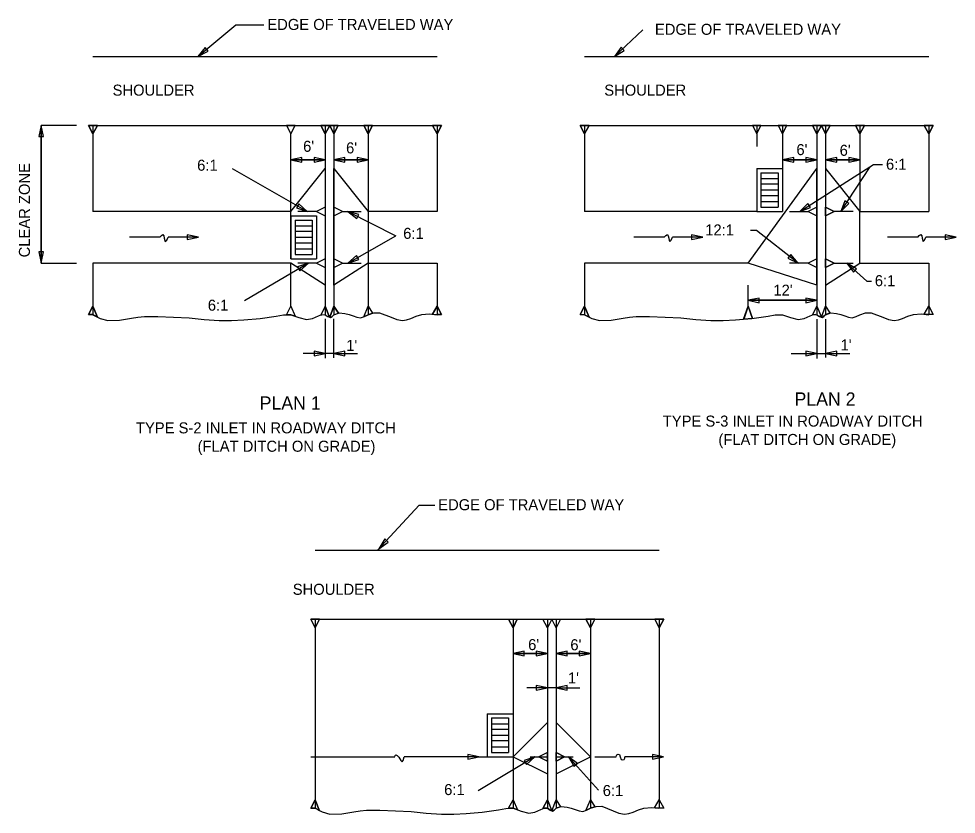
# Model space of a CAD drawing. Extents: x -437.4 to -407.9, y -458.1 to -438.
# Drawn here: x -437.39 to -424.64, y -448.87 to -438.05 of the extents above; entities that cross this region are included whole.
import ezdxf

# ---------------------------------------------------------------- set-up
doc = ezdxf.new("R2010")
doc.units = 0
for name, color, linetype in [('Common-Notes', 7, 'Continuous'), ('Level 4', 7, 'Continuous'), ('Level 45', 7, 'Continuous')]:
    doc.layers.add(name, color=color, linetype=linetype)

msp = doc.modelspace()

# ---------------------------------------------------------------- linework, layer by layer
at = {"layer": 'Level 4'}
for p, q in [((-434.95, -438.564), (-434.433, -438.133)), ((-434.433, -438.133), (-434.053, -438.133)), ((-429.285, -438.564), (-428.902, -438.202)), ((-436.378, -438.564), (-431.699, -438.564)), ((-429.692, -438.564), (-425.013, -438.564)), ((-436.604, -439.499), (-437.081, -439.499)), ((-437.08, -441.372), (-437.08, -439.5)), ((-437.08, -439.5), (-437.08, -441.372)), ((-436.378, -439.616), (-436.439, -439.499)), ((-436.439, -439.499), (-436.378, -439.499)), ((-436.378, -439.499), (-431.699, -439.499)), ((-436.318, -439.499), (-436.378, -439.616)), ((-436.378, -439.499), (-436.378, -440.67)), ((-433.746, -439.499), (-433.687, -439.616)), ((-433.687, -439.616), (-433.63, -439.499)), ((-433.22, -439.616), (-433.28, -439.499)), ((-433.159, -439.499), (-433.22, -439.616)), ((-433.22, -439.499), (-433.22, -442.073)), ((-433.103, -439.616), (-433.159, -439.499)), ((-433.042, -439.499), (-433.103, -439.616)), ((-433.103, -439.499), (-433.103, -442.073)), ((-432.635, -439.616), (-432.696, -439.499)), ((-432.575, -439.499), (-432.635, -439.616)), ((-432.635, -439.499), (-432.635, -442.073)), ((-431.699, -439.616), (-431.76, -439.499)), ((-431.699, -439.499), (-431.639, -439.499)), ((-431.639, -439.499), (-431.699, -439.616)), ((-431.699, -439.499), (-431.699, -440.67)), ((-429.692, -439.616), (-429.753, -439.499)), ((-429.753, -439.499), (-429.692, -439.499)), ((-429.692, -439.499), (-425.013, -439.499)), ((-429.632, -439.499), (-429.692, -439.616)), ((-429.692, -439.499), (-429.692, -440.67)), ((-427.411, -439.499), (-427.352, -439.616)), ((-427.352, -439.616), (-427.294, -439.499)), ((-427.352, -439.499), (-427.352, -439.785)), ((-427.06, -439.499), (-427.001, -439.616)), ((-427.001, -439.616), (-426.944, -439.499)), ((-427.001, -439.499), (-427.001, -440.67)), ((-426.534, -439.616), (-426.594, -439.499)), ((-426.473, -439.499), (-426.534, -439.616)), ((-426.534, -439.499), (-426.534, -442.073)), ((-426.417, -439.616), (-426.473, -439.499)), ((-426.355, -439.499), (-426.417, -439.616)), ((-426.417, -439.499), (-426.417, -442.073)), ((-425.948, -439.616), (-426.01, -439.499)), ((-425.888, -439.499), (-425.948, -439.616)), ((-425.948, -439.499), (-425.948, -440.67)), ((-425.013, -439.616), (-425.074, -439.499)), ((-425.013, -439.499), (-424.953, -439.499)), ((-424.953, -439.499), (-425.013, -439.616)), ((-425.013, -439.499), (-425.013, -440.67)), ((-433.687, -440.67), (-433.687, -439.616)), ((-433.688, -439.968), (-433.22, -439.968)), ((-433.22, -439.968), (-433.688, -439.968)), ((-433.103, -439.968), (-432.635, -439.968)), ((-432.635, -439.968), (-433.103, -439.968)), ((-427.001, -439.968), (-426.534, -439.968)), ((-426.534, -439.968), (-427.001, -439.968)), ((-426.767, -440.67), (-425.766, -440.033)), ((-426.417, -439.968), (-425.949, -439.968)), ((-425.949, -439.968), (-426.417, -439.968)), ((-426.209, -440.67), (-425.811, -440.061)), ((-425.766, -440.033), (-425.64, -440.033)), ((-433.463, -440.67), (-434.48, -440.09)), ((-433.687, -440.67), (-433.22, -440.085)), ((-433.22, -440.085), (-433.22, -441.671)), ((-433.103, -441.671), (-433.103, -440.085)), ((-433.103, -440.085), (-432.635, -440.67)), ((-427.469, -441.372), (-426.534, -440.085)), ((-427.352, -440.085), (-427.001, -440.085)), ((-427.352, -440.085), (-427.352, -440.67)), ((-427.294, -440.143), (-427.06, -440.143)), ((-427.294, -440.143), (-427.294, -440.612)), ((-427.06, -440.143), (-427.06, -440.612)), ((-427.001, -440.085), (-427.001, -440.67)), ((-426.534, -441.671), (-426.534, -440.085)), ((-426.417, -440.085), (-425.948, -440.67)), ((-426.417, -440.085), (-426.417, -441.671)), ((-427.294, -440.221), (-427.06, -440.221)), ((-427.06, -440.3), (-427.294, -440.3)), ((-427.294, -440.377), (-427.06, -440.377)), ((-427.06, -440.455), (-427.294, -440.455)), ((-427.294, -440.533), (-427.06, -440.533)), ((-433.687, -440.67), (-436.378, -440.67)), ((-433.687, -441.313), (-433.687, -440.67)), ((-433.337, -440.67), (-433.594, -440.67)), ((-433.22, -440.612), (-433.337, -440.67)), ((-433.337, -440.67), (-433.22, -440.729)), ((-432.986, -440.67), (-433.103, -440.612)), ((-433.103, -440.729), (-432.986, -440.67)), ((-432.986, -440.67), (-432.729, -440.67)), ((-432.912, -440.67), (-432.26, -441.003)), ((-432.635, -440.67), (-432.635, -441.372)), ((-431.699, -440.67), (-432.635, -440.67)), ((-427.352, -440.67), (-429.692, -440.67)), ((-427.352, -440.67), (-427.001, -440.67)), ((-427.294, -440.612), (-427.06, -440.612)), ((-426.908, -440.67), (-426.651, -440.67)), ((-426.534, -440.612), (-426.651, -440.67)), ((-426.651, -440.67), (-426.534, -440.729)), ((-426.3, -440.67), (-426.417, -440.612)), ((-426.417, -440.729), (-426.3, -440.67)), ((-426.042, -440.67), (-426.3, -440.67)), ((-425.948, -441.372), (-425.948, -440.67)), ((-425.948, -440.67), (-425.013, -440.67)), ((-433.687, -440.729), (-433.687, -441.313)), ((-433.687, -440.729), (-433.337, -440.729)), ((-433.63, -440.786), (-433.396, -440.786)), ((-433.63, -440.786), (-433.63, -441.255)), ((-433.396, -440.786), (-433.396, -441.255)), ((-433.337, -440.729), (-433.337, -441.313)), ((-433.63, -440.865), (-433.396, -440.865)), ((-433.396, -440.943), (-433.63, -440.943)), ((-427.357, -440.927), (-427.435, -440.927)), ((-426.788, -441.372), (-427.357, -440.927)), ((-435.469, -441.02), (-435.88, -441.02)), ((-434.945, -441.021), (-435.357, -441.021)), ((-433.63, -441.02), (-433.396, -441.02)), ((-433.396, -441.099), (-433.63, -441.099)), ((-432.911, -441.372), (-432.26, -441.003)), ((-428.609, -441.02), (-429.021, -441.02)), ((-428.085, -441.021), (-428.497, -441.021)), ((-425.163, -441.02), (-425.574, -441.02)), ((-424.638, -441.021), (-425.05, -441.021)), ((-433.63, -441.177), (-433.396, -441.177)), ((-433.687, -441.313), (-433.337, -441.313)), ((-433.63, -441.255), (-433.396, -441.255)), ((-433.22, -441.313), (-433.337, -441.372)), ((-432.986, -441.372), (-433.103, -441.313)), ((-426.534, -441.313), (-426.651, -441.372)), ((-426.3, -441.372), (-426.417, -441.313)), ((-437.081, -441.372), (-436.604, -441.372)), ((-436.378, -441.372), (-436.378, -442.073)), ((-433.687, -441.372), (-436.378, -441.372)), ((-433.449, -441.372), (-434.315, -441.883)), ((-433.22, -441.671), (-433.687, -441.372)), ((-433.687, -441.957), (-433.687, -441.372)), ((-433.337, -441.372), (-433.594, -441.372)), ((-433.337, -441.372), (-433.22, -441.43)), ((-432.635, -441.372), (-433.103, -441.671)), ((-433.103, -441.43), (-432.986, -441.372)), ((-432.986, -441.372), (-432.729, -441.372)), ((-432.635, -441.372), (-431.699, -441.372)), ((-431.699, -441.372), (-431.699, -442.073)), ((-429.692, -441.372), (-429.692, -442.073)), ((-427.469, -441.372), (-429.692, -441.372)), ((-426.534, -441.671), (-427.469, -441.372)), ((-426.651, -441.372), (-426.908, -441.372)), ((-426.651, -441.372), (-426.534, -441.43)), ((-426.417, -441.671), (-425.948, -441.372)), ((-426.417, -441.43), (-426.3, -441.372)), ((-426.3, -441.372), (-426.042, -441.372)), ((-426.128, -441.372), (-425.854, -441.618)), ((-425.948, -441.372), (-425.013, -441.372)), ((-425.013, -441.372), (-425.013, -442.073)), ((-427.469, -441.957), (-427.469, -441.671)), ((-425.854, -441.618), (-425.792, -441.618)), ((-436.378, -441.957), (-436.439, -442.073)), ((-436.318, -442.106), (-436.378, -441.957)), ((-433.748, -442.074), (-433.687, -441.957)), ((-433.687, -441.957), (-433.628, -442.094)), ((-433.22, -441.957), (-433.281, -442.078)), ((-433.22, -441.957), (-433.161, -442.106)), ((-433.158, -442.107), (-433.103, -441.957)), ((-433.103, -441.957), (-433.041, -442.052)), ((-432.695, -442.103), (-432.635, -441.957)), ((-432.635, -441.957), (-432.575, -442.051)), ((-431.76, -442.064), (-431.699, -441.957)), ((-431.699, -441.957), (-431.639, -442.073)), ((-429.692, -441.957), (-429.753, -442.073)), ((-429.632, -442.106), (-429.692, -441.957)), ((-427.469, -441.957), (-427.528, -442.135)), ((-427.469, -441.878), (-426.534, -441.878)), ((-426.534, -441.878), (-427.469, -441.878)), ((-427.411, -442.126), (-427.469, -441.957)), ((-426.534, -441.957), (-426.594, -442.076)), ((-426.534, -441.957), (-426.473, -442.109)), ((-426.473, -442.109), (-426.417, -441.957)), ((-426.417, -441.957), (-426.356, -442.05)), ((-425.075, -442.066), (-425.013, -441.957)), ((-425.013, -441.957), (-424.953, -442.073)), ((-436.439, -442.073), (-436.378, -442.073)), ((-431.639, -442.073), (-431.699, -442.073)), ((-429.753, -442.073), (-429.692, -442.073)), ((-424.953, -442.073), (-425.013, -442.073)), ((-433.22, -442.128), (-433.22, -442.666)), ((-433.103, -442.658), (-433.103, -442.128)), ((-426.534, -442.134), (-426.534, -442.669)), ((-426.417, -442.134), (-426.417, -442.656)), ((-433.103, -442.602), (-433.521, -442.602)), ((-433.103, -442.602), (-432.781, -442.602)), ((-426.882, -442.602), (-426.086, -442.602)), ((-432.509, -445.276), (-431.944, -444.663)), ((-431.944, -444.663), (-431.73, -444.663)), ((-433.357, -445.275), (-428.678, -445.275)), ((-433.357, -446.329), (-433.417, -446.212)), ((-433.417, -446.212), (-433.357, -446.212)), ((-433.296, -446.212), (-433.357, -446.329)), ((-433.357, -446.212), (-433.357, -448.784)), ((-433.357, -446.212), (-428.678, -446.212)), ((-430.725, -446.212), (-430.666, -446.329)), ((-430.666, -446.329), (-430.608, -446.212)), ((-430.666, -446.212), (-430.666, -448.785)), ((-430.198, -446.329), (-430.259, -446.212)), ((-430.138, -446.212), (-430.198, -446.329)), ((-430.198, -446.212), (-430.198, -448.784)), ((-430.081, -446.329), (-430.138, -446.212)), ((-430.021, -446.212), (-430.081, -446.329)), ((-430.081, -446.212), (-430.081, -448.784)), ((-429.613, -446.329), (-429.674, -446.212)), ((-429.552, -446.212), (-429.614, -446.329)), ((-429.614, -446.212), (-429.614, -448.784)), ((-428.678, -446.329), (-428.738, -446.212)), ((-428.678, -446.212), (-428.617, -446.212)), ((-428.617, -446.212), (-428.678, -446.329)), ((-428.678, -446.212), (-428.678, -448.784)), ((-430.666, -446.679), (-430.198, -446.679)), ((-430.198, -446.679), (-430.666, -446.679)), ((-430.081, -446.679), (-429.613, -446.679)), ((-429.613, -446.679), (-430.081, -446.679)), ((-430.081, -447.147), (-430.476, -447.147)), ((-430.081, -447.147), (-429.758, -447.147)), ((-431.016, -447.499), (-431.016, -448.083)), ((-431.016, -447.499), (-430.666, -447.499)), ((-430.959, -447.557), (-430.725, -447.557)), ((-430.959, -447.557), (-430.959, -448.024)), ((-430.725, -447.557), (-430.725, -448.024)), ((-430.666, -447.499), (-430.666, -448.083)), ((-430.959, -447.635), (-430.725, -447.635)), ((-430.725, -447.713), (-430.959, -447.713)), ((-430.198, -447.616), (-430.666, -448.083)), ((-430.198, -447.616), (-430.198, -448.317)), ((-429.614, -448.083), (-430.081, -447.616)), ((-430.081, -447.616), (-430.081, -448.317)), ((-430.959, -447.79), (-430.725, -447.79)), ((-430.725, -447.869), (-430.959, -447.869)), ((-430.959, -447.947), (-430.725, -447.947)), ((-433.416, -448.083), (-432.275, -448.083)), ((-431.129, -448.083), (-432.148, -448.083)), ((-430.367, -448.083), (-431.141, -448.549)), ((-431.129, -448.083), (-431.016, -448.083)), ((-431.016, -448.083), (-430.666, -448.083)), ((-430.959, -448.024), (-430.725, -448.024)), ((-430.666, -448.083), (-430.198, -448.317)), ((-430.432, -448.083), (-430.198, -448.083)), ((-430.198, -448.024), (-430.315, -448.083)), ((-430.315, -448.083), (-430.198, -448.142)), ((-429.965, -448.083), (-430.081, -448.024)), ((-430.081, -448.317), (-429.613, -448.083)), ((-430.081, -448.083), (-429.848, -448.083)), ((-430.081, -448.142), (-429.965, -448.083)), ((-429.912, -448.083), (-429.503, -448.538)), ((-429.555, -448.083), (-429.262, -448.083)), ((-428.619, -448.083), (-429.145, -448.083)), ((-433.357, -448.668), (-433.417, -448.784)), ((-433.296, -448.819), (-433.357, -448.668)), ((-430.727, -448.785), (-430.666, -448.668)), ((-430.666, -448.668), (-430.607, -448.806)), ((-430.198, -448.668), (-430.259, -448.789)), ((-430.198, -448.668), (-430.14, -448.817)), ((-430.137, -448.818), (-430.081, -448.668)), ((-430.081, -448.668), (-430.019, -448.764)), ((-429.674, -448.815), (-429.614, -448.668)), ((-429.613, -448.668), (-429.551, -448.765)), ((-428.74, -448.778), (-428.678, -448.668)), ((-428.678, -448.668), (-428.617, -448.784)), ((-433.417, -448.784), (-433.357, -448.784)), ((-428.617, -448.784), (-428.683, -448.784))]:
    msp.add_line(p, q, dxfattribs=at)
for points in [[(-434.854, -438.442), (-434.95, -438.564), (-434.813, -438.491)], [(-429.196, -438.437), (-429.285, -438.564), (-429.153, -438.483)], [(-437.049, -439.652), (-437.08, -439.5), (-437.112, -439.652)], [(-436.439, -439.499), (-436.378, -439.616), (-436.318, -439.499)], [(-433.746, -439.499), (-433.687, -439.616), (-433.63, -439.499)], [(-433.28, -439.499), (-433.22, -439.616), (-433.159, -439.499)], [(-433.159, -439.499), (-433.103, -439.616), (-433.042, -439.499)], [(-432.696, -439.499), (-432.635, -439.616), (-432.575, -439.499)], [(-431.76, -439.499), (-431.699, -439.616), (-431.639, -439.499)], [(-429.753, -439.499), (-429.692, -439.616), (-429.632, -439.499)], [(-427.411, -439.499), (-427.352, -439.616), (-427.294, -439.499)], [(-427.06, -439.499), (-427.001, -439.616), (-426.944, -439.499)], [(-426.594, -439.499), (-426.534, -439.616), (-426.473, -439.499)], [(-426.473, -439.499), (-426.417, -439.616), (-426.355, -439.499)], [(-426.01, -439.499), (-425.948, -439.616), (-425.888, -439.499)], [(-425.074, -439.499), (-425.013, -439.616), (-424.953, -439.499)], [(-433.536, -439.936), (-433.688, -439.968), (-433.536, -439.999)], [(-433.372, -439.999), (-433.22, -439.968), (-433.372, -439.936)], [(-432.951, -439.936), (-433.103, -439.968), (-432.951, -439.999)], [(-432.787, -439.999), (-432.635, -439.968), (-432.787, -439.936)], [(-426.849, -439.936), (-427.001, -439.968), (-426.849, -439.999)], [(-426.686, -439.999), (-426.534, -439.968), (-426.686, -439.936)], [(-426.264, -439.936), (-426.417, -439.968), (-426.264, -439.999)], [(-426.101, -439.999), (-425.949, -439.968), (-426.101, -439.936)], [(-433.611, -440.622), (-433.463, -440.67), (-433.58, -440.567)], [(-426.656, -440.561), (-426.767, -440.67), (-426.622, -440.615)], [(-426.152, -440.525), (-426.209, -440.67), (-426.099, -440.56)], [(-432.763, -440.711), (-432.912, -440.67), (-432.791, -440.767)], [(-426.534, -440.612), (-426.651, -440.67), (-426.534, -440.729)], [(-426.417, -440.612), (-426.3, -440.67), (-426.417, -440.729)], [(-435.097, -441.052), (-434.945, -441.021), (-435.097, -440.989)], [(-428.237, -441.052), (-428.085, -441.021), (-428.237, -440.989)], [(-424.791, -441.052), (-424.638, -441.021), (-424.791, -440.989)], [(-437.112, -441.219), (-437.08, -441.372), (-437.049, -441.219)], [(-432.794, -441.27), (-432.911, -441.372), (-432.763, -441.325)], [(-426.927, -441.303), (-426.788, -441.372), (-426.888, -441.253)], [(-426.534, -441.313), (-426.651, -441.372), (-426.534, -441.43)], [(-426.417, -441.313), (-426.3, -441.372), (-426.417, -441.43)], [(-433.564, -441.477), (-433.449, -441.372), (-433.596, -441.422)], [(-425.993, -441.45), (-426.128, -441.372), (-426.036, -441.497)], [(-427.317, -441.847), (-427.469, -441.878), (-427.317, -441.91)], [(-426.686, -441.91), (-426.534, -441.878), (-426.686, -441.847)], [(-436.439, -442.073), (-436.378, -441.957), (-436.318, -442.106), (-436.378, -442.073)], [(-433.748, -442.074), (-433.687, -441.957), (-433.628, -442.094), (-433.688, -442.074)], [(-433.161, -442.106), (-433.22, -441.957), (-433.281, -442.078), (-433.265, -442.072), (-433.22, -442.074), (-433.183, -442.097)], [(-433.041, -442.052), (-433.103, -441.957), (-433.158, -442.107), (-433.15, -442.11), (-433.127, -442.096), (-433.103, -442.074)], [(-432.695, -442.103), (-432.635, -441.957), (-432.575, -442.051), (-432.635, -442.074), (-432.687, -442.1)], [(-431.639, -442.073), (-431.699, -441.957), (-431.76, -442.064), (-431.699, -442.073)], [(-429.753, -442.073), (-429.692, -441.957), (-429.632, -442.106), (-429.692, -442.074)], [(-427.53, -442.135), (-427.469, -441.957), (-427.411, -442.126)], [(-426.594, -442.076), (-426.534, -441.957), (-426.473, -442.109), (-426.556, -442.073)], [(-426.473, -442.109), (-426.417, -441.957), (-426.356, -442.05), (-426.417, -442.074), (-426.463, -442.11), (-426.48, -442.103)], [(-425.075, -442.066), (-425.013, -441.957), (-424.953, -442.073), (-425.013, -442.073)], [(-433.372, -442.633), (-433.22, -442.602), (-433.372, -442.57)], [(-432.951, -442.57), (-433.103, -442.602), (-432.951, -442.633)], [(-426.686, -442.633), (-426.534, -442.602), (-426.686, -442.57)], [(-426.264, -442.57), (-426.417, -442.602), (-426.264, -442.633)], [(-432.41, -445.122), (-432.49, -445.255), (-432.364, -445.165)], [(-433.417, -446.212), (-433.357, -446.329), (-433.296, -446.212)], [(-430.608, -446.212), (-430.666, -446.329), (-430.725, -446.212)], [(-430.138, -446.212), (-430.198, -446.329), (-430.259, -446.212)], [(-430.021, -446.212), (-430.081, -446.329), (-430.138, -446.212)], [(-429.674, -446.212), (-429.613, -446.329), (-429.552, -446.212)], [(-428.738, -446.212), (-428.678, -446.329), (-428.617, -446.212)], [(-430.514, -446.648), (-430.666, -446.679), (-430.514, -446.711)], [(-430.35, -446.711), (-430.198, -446.679), (-430.35, -446.648)], [(-429.929, -446.648), (-430.081, -446.679), (-429.929, -446.711)], [(-429.765, -446.711), (-429.613, -446.679), (-429.765, -446.648)], [(-430.35, -447.179), (-430.198, -447.147), (-430.35, -447.116)], [(-429.929, -447.116), (-430.081, -447.147), (-429.929, -447.179)], [(-431.281, -448.115), (-431.129, -448.083), (-431.281, -448.052)], [(-430.481, -448.189), (-430.367, -448.083), (-430.513, -448.135)], [(-430.198, -448.024), (-430.315, -448.083), (-430.198, -448.142)], [(-430.081, -448.024), (-429.965, -448.083), (-430.081, -448.142)], [(-429.787, -448.175), (-429.912, -448.083), (-429.834, -448.217)], [(-428.771, -448.115), (-428.619, -448.083), (-428.771, -448.052)], [(-433.417, -448.784), (-433.357, -448.668), (-433.296, -448.819), (-433.357, -448.784)], [(-430.727, -448.785), (-430.666, -448.668), (-430.607, -448.806), (-430.666, -448.785), (-430.715, -448.785)], [(-430.259, -448.789), (-430.198, -448.668), (-430.14, -448.817), (-430.161, -448.808), (-430.198, -448.785), (-430.243, -448.783)], [(-430.137, -448.818), (-430.081, -448.668), (-430.019, -448.764), (-430.081, -448.785), (-430.105, -448.808), (-430.128, -448.822)], [(-429.674, -448.815), (-429.614, -448.668), (-429.551, -448.765), (-429.613, -448.785), (-429.665, -448.812)], [(-428.74, -448.778), (-428.678, -448.668), (-428.617, -448.784), (-428.683, -448.784)]]:
    msp.add_lwpolyline(points, close=True, dxfattribs=at)
for points in [[(-435.469, -441.021), (-435.448, -440.995), (-435.427, -440.983), (-435.415, -440.999), (-435.408, -441.032), (-435.402, -441.064), (-435.394, -441.08), (-435.375, -441.059), (-435.357, -441.021)], [(-428.609, -441.021), (-428.588, -440.995), (-428.567, -440.983), (-428.555, -440.999), (-428.548, -441.032), (-428.542, -441.064), (-428.534, -441.08), (-428.515, -441.059), (-428.497, -441.021)], [(-425.163, -441.021), (-425.142, -440.995), (-425.12, -440.983), (-425.108, -440.999), (-425.101, -441.032), (-425.095, -441.064), (-425.087, -441.08), (-425.068, -441.059), (-425.05, -441.021)], [(-436.378, -442.074), (-436.281, -442.123), (-436.177, -442.153), (-436.016, -442.149), (-435.854, -442.119), (-435.766, -442.106), (-435.679, -442.098), (-435.588, -442.097), (-435.497, -442.099), (-435.284, -442.105), (-435.071, -442.116), (-434.867, -442.138), (-434.662, -442.154), (-434.494, -442.153), (-434.327, -442.143), (-434.106, -442.126), (-433.885, -442.093), (-433.786, -442.074), (-433.688, -442.074), (-433.579, -442.111), (-433.472, -442.14), (-433.392, -442.125), (-433.31, -442.089), (-433.265, -442.072), (-433.22, -442.074), (-433.183, -442.097), (-433.15, -442.11), (-433.127, -442.096), (-433.103, -442.074), (-433.031, -442.049), (-432.953, -442.059), (-432.896, -442.072), (-432.841, -442.089), (-432.79, -442.108), (-432.739, -442.116), (-432.687, -442.1), (-432.635, -442.074), (-432.558, -442.048), (-432.48, -442.046), (-432.324, -442.106), (-432.247, -442.139), (-432.169, -442.153), (-432.112, -442.144), (-432.056, -442.125), (-431.982, -442.095), (-431.907, -442.071), (-431.804, -442.061), (-431.699, -442.074)], [(-429.692, -442.074), (-429.595, -442.123), (-429.491, -442.153), (-429.33, -442.149), (-429.168, -442.119), (-429.08, -442.106), (-428.992, -442.098), (-428.901, -442.097), (-428.81, -442.099), (-428.597, -442.105), (-428.385, -442.116), (-428.18, -442.138), (-427.975, -442.154), (-427.808, -442.153), (-427.641, -442.143), (-427.42, -442.126), (-427.198, -442.093), (-427.099, -442.074), (-427.001, -442.074), (-426.893, -442.111), (-426.786, -442.14), (-426.706, -442.125), (-426.624, -442.089), (-426.578, -442.072), (-426.534, -442.074), (-426.497, -442.097), (-426.463, -442.11), (-426.44, -442.096), (-426.417, -442.074), (-426.345, -442.049), (-426.266, -442.059), (-426.209, -442.072), (-426.154, -442.089), (-426.103, -442.108), (-426.053, -442.116), (-426.001, -442.1), (-425.949, -442.074), (-425.872, -442.048), (-425.794, -442.046), (-425.638, -442.106), (-425.561, -442.139), (-425.483, -442.153), (-425.426, -442.144), (-425.369, -442.125), (-425.295, -442.095), (-425.221, -442.071), (-425.117, -442.061), (-425.013, -442.074)], [(-432.275, -448.083), (-432.268, -448.069), (-432.259, -448.059), (-432.24, -448.065), (-432.22, -448.091), (-432.193, -448.137), (-432.172, -448.154), (-432.16, -448.133), (-432.148, -448.083)], [(-429.262, -448.083), (-429.26, -448.069), (-429.252, -448.057), (-429.236, -448.05), (-429.219, -448.052), (-429.208, -448.083), (-429.197, -448.12), (-429.176, -448.127), (-429.154, -448.121), (-429.146, -448.104), (-429.145, -448.083)], [(-433.357, -448.785), (-433.259, -448.835), (-433.155, -448.864), (-432.994, -448.861), (-432.832, -448.831), (-432.745, -448.817), (-432.657, -448.81), (-432.566, -448.809), (-432.475, -448.811), (-432.262, -448.817), (-432.049, -448.828), (-431.845, -448.849), (-431.64, -448.866), (-431.472, -448.865), (-431.305, -448.855), (-431.084, -448.838), (-430.863, -448.805), (-430.764, -448.786), (-430.666, -448.785), (-430.557, -448.823), (-430.451, -448.852), (-430.371, -448.836), (-430.288, -448.801), (-430.243, -448.783), (-430.198, -448.785), (-430.161, -448.808), (-430.128, -448.822), (-430.105, -448.808), (-430.081, -448.785), (-430.009, -448.761), (-429.931, -448.77), (-429.874, -448.783), (-429.819, -448.801), (-429.768, -448.82), (-429.717, -448.828), (-429.665, -448.812), (-429.613, -448.785), (-429.536, -448.76), (-429.458, -448.758), (-429.302, -448.817), (-429.226, -448.85), (-429.148, -448.864), (-429.091, -448.856), (-429.034, -448.837), (-428.96, -448.807), (-428.885, -448.782), (-428.782, -448.773), (-428.683, -448.784)]]:
    msp.add_lwpolyline(points, dxfattribs=at)

# ---------------------------------------------------------------- texts
at = {"layer": 'Common-Notes'}
for s, p in [('PLAN 2', (-426.838, -443.31)), ('PLAN 1', (-434.111, -443.364))]:
    msp.add_text(s, height=0.18, dxfattribs=at).set_placement(p)
at = {"layer": 'Level 4'}
for s, p in [('EDGE OF TRAVELED WAY', (-434.007, -438.202)), ('EDGE OF TRAVELED WAY', (-428.736, -438.268)), ('SHOULDER', (-436.111, -439.095)), ('SHOULDER', (-429.425, -439.095)), ('TYPE S-3 INLET IN ROADWAY DITCH', (-428.629, -443.595)), ('TYPE S-2 INLET IN ROADWAY DITCH ', (-435.793, -443.687)), ('(FLAT DITCH ON GRADE)', (-434.955, -443.937)), ('(FLAT DITCH ON GRADE)', (-427.873, -443.845)), ('EDGE OF TRAVELED WAY', (-431.683, -444.732)), ('SHOULDER', (-433.661, -445.882))]:
    msp.add_text(s, height=0.15, dxfattribs=at).set_placement(p)
msp.add_text('CLEAR ZONE', height=0.15, rotation=90, dxfattribs=at).set_placement((-437.235, -441.294))
at = {"layer": 'Level 45'}
for s, p in [("6'", (-433.52, -439.859)), ("6'", (-432.936, -439.88)), ("6'", (-426.812, -439.904)), ("6'", (-426.224, -439.913)), ('6:1', (-425.594, -440.102)), ('6:1', (-434.961, -440.116)), ('12:1', (-428.052, -440.996)), ('6:1', (-432.159, -441.042)), ('6:1', (-425.746, -441.686)), ("12'", (-427.125, -441.815)), ('6:1', (-434.816, -442.019)), ("1'", (-432.934, -442.566)), ("1'", (-426.212, -442.56)), ("6'", (-430.46, -446.634)), ("6'", (-429.886, -446.636)), ("1'", (-429.919, -447.087)), ('6:1', (-431.602, -448.605)), ('6:1', (-429.446, -448.618))]:
    msp.add_text(s, height=0.15, dxfattribs=at).set_placement(p)

doc.saveas('drawing.dxf')
